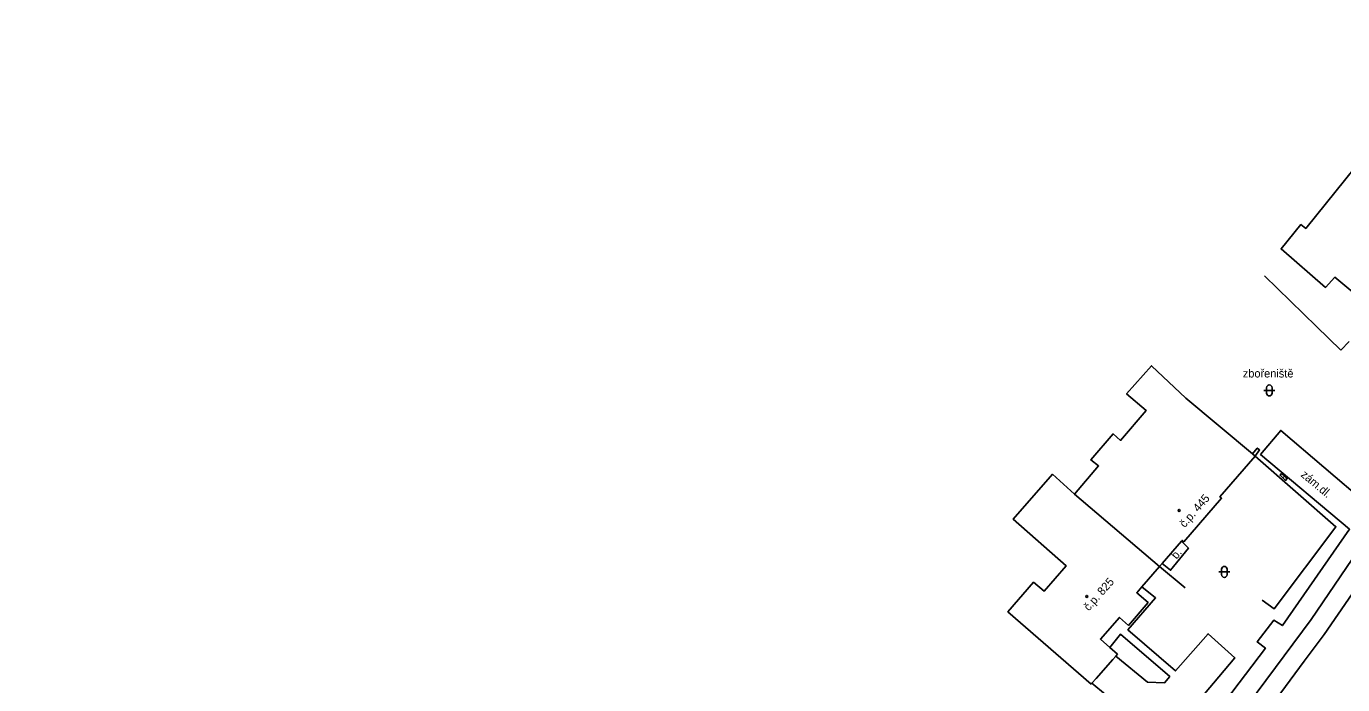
# Model space of a CAD drawing. Extents: x -577457 to -568404, y -1208466 to -1201387.
# Drawn here: x -569192.7 to -569072.5, y -1204568.7 to -1204508.6 of the extents above; entities that cross this region are included whole.
import ezdxf

# ---------------------------------------------------------------- set-up
doc = ezdxf.new("R2010")
doc.units = 0
for name, color, linetype in [('BUDOVY_MĚŘ', 7, 'Continuous'), ('BUDOVY_NEMĚŘ', 7, 'Continuous'), ('OBVOD_PILÍŘE', 7, 'Continuous'), ('POMOC_POPIS', 7, 'Continuous'), ('ROZHRANÍ_PLOCH', 7, 'Continuous'), ('ZN_BUDOV', 7, 'Continuous'), ('ZN_DOPLŇKOVÉ', 7, 'Continuous'), ('ZN_KULTUR', 7, 'Continuous'), ('Č_POPIS_ORIENT', 7, 'Continuous')]:
    doc.layers.add(name, color=color, linetype=linetype)

msp = doc.modelspace()

# ---------------------------------------------------------------- linework, layer by layer
at = {"layer": 'BUDOVY_MĚŘ'}
for points in [[(-569080.72, -1204547.68), (-569080.49, -1204547.88)], [(-569087.2, -1204555.63), (-569087.15, -1204555.57), (-569087.01, -1204555.69), (-569083.54, -1204551.72), (-569083.7, -1204551.59), (-569080.49, -1204547.88)], [(-569089.21, -1204557.96), (-569090.83, -1204559.82)], [(-569089.21, -1204557.96), (-569088.97, -1204557.68)], [(-569090.83, -1204559.82), (-569091.29, -1204560.36), (-569090.26, -1204561.25), (-569092.06, -1204563.33), (-569092.88, -1204562.61), (-569094.62, -1204564.58), (-569093.76, -1204565.34)], [(-569093.76, -1204565.34), (-569093.05, -1204565.97)], [(-569093.2, -1204566.15), (-569093.48, -1204566.46)], [(-569093.05, -1204565.97), (-569093.2, -1204566.15)], [(-569095.39, -1204568.62), (-569095.01, -1204568.19)], [(-569095.39, -1204568.62), (-569095.47, -1204568.71)]]:
    msp.add_lwpolyline(points, dxfattribs=at)
at = {"layer": 'BUDOVY_NEMĚŘ'}
for points in [[(-569071.32, -1204521.47), (-569075.86, -1204527.09), (-569076.3, -1204526.74), (-569078.11, -1204528.96), (-569074.05, -1204532.48), (-569073.21, -1204531.55), (-569069.56, -1204534.58)], [(-569080.72, -1204547.68), (-569086.8, -1204542.59), (-569089.96, -1204539.63), (-569092.23, -1204542.18), (-569090.45, -1204543.71), (-569092.78, -1204546.44), (-569093.46, -1204545.85), (-569095.48, -1204548.22), (-569094.78, -1204548.78), (-569096.99, -1204551.35)], [(-569096.99, -1204551.35), (-569098.98, -1204549.54), (-569102.6, -1204553.63), (-569097.73, -1204557.9), (-569099.76, -1204560.22), (-569100.72, -1204559.4), (-569103.07, -1204562.09), (-569095.47, -1204568.71)], [(-569096.99, -1204551.35), (-569089.21, -1204557.96)]]:
    msp.add_lwpolyline(points, dxfattribs=at)
at = {"layer": 'OBVOD_PILÍŘE'}
for points in [[(-569077.92, -1204549.59), (-569078.07, -1204549.46), (-569078.21, -1204549.62), (-569077.94, -1204549.87), (-569077.79, -1204549.71), (-569077.92, -1204549.59)], [(-569077.67, -1204549.82), (-569077.79, -1204549.71), (-569077.94, -1204549.87), (-569077.7, -1204550.09), (-569077.55, -1204549.93), (-569077.67, -1204549.82)]]:
    msp.add_lwpolyline(points, dxfattribs=at)
at = {"layer": 'ROZHRANÍ_PLOCH'}
for points in [[(-569041.21, -1204508.64), (-569040.59, -1204509.58), (-569040.25, -1204510.21), (-569039.93, -1204511.4), (-569039.84, -1204512.36), (-569040.05, -1204513.31), (-569040.29, -1204513.88), (-569040.51, -1204513.8), (-569043.68, -1204518.74), (-569050.87, -1204529.62), (-569059.42, -1204542.46), (-569063.61, -1204548.77), (-569066.83, -1204553.51), (-569074.19, -1204564.16), (-569076.01, -1204566.61), (-569079, -1204570.64)], [(-569193.54, -1204654.14), (-569180.57, -1204647.46), (-569168.09, -1204641.22), (-569155.65, -1204634.81), (-569151.19, -1204632.37), (-569146.32, -1204629.48), (-569140.18, -1204625.55), (-569133.63, -1204621.26), (-569127.76, -1204617.05), (-569123.45, -1204613.78), (-569117.55, -1204608.82), (-569108.26, -1204600.74), (-569100.71, -1204593.46), (-569095.2, -1204587.67), (-569088.24, -1204579.64), (-569082.76, -1204572.74), (-569075.37, -1204562.81), (-569068.38, -1204552.55), (-569060.81, -1204541.45), (-569052.52, -1204528.77), (-569045.02, -1204517.63), (-569041.38, -1204511.96), (-569040.25, -1204510.21)], [(-569065.63, -1204542.48), (-569065.75, -1204542.69), (-569064.6, -1204543.84), (-569070.27, -1204552.24), (-569078.14, -1204545.53), (-569079.98, -1204547.72), (-569071.85, -1204554.55), (-569077.99, -1204563.35), (-569078.76, -1204562.85), (-569080.29, -1204564.84), (-569079.54, -1204565.42), (-569085.02, -1204572.63)], [(-569088.97, -1204557.68), (-569088.21, -1204558.3), (-569086.57, -1204556.27), (-569087.2, -1204555.63)], [(-569090.83, -1204559.82), (-569089.58, -1204560.82), (-569092.11, -1204563.73), (-569087.76, -1204567.49), (-569084.78, -1204564.1), (-569082.33, -1204566.3), (-569086.56, -1204571.33), (-569087.6, -1204570.5), (-569087.76, -1204570.73), (-569085.69, -1204572.64), (-569085.43, -1204572.32), (-569085.02, -1204572.63)], [(-569093.76, -1204565.34), (-569092.79, -1204564.15), (-569088.28, -1204568.01), (-569088.75, -1204568.57), (-569090.32, -1204568.52), (-569093.2, -1204566.15)], [(-569095.39, -1204568.62), (-569090.4, -1204572.75), (-569089.94, -1204572.78), (-569087.13, -1204575.33)]]:
    msp.add_lwpolyline(points, dxfattribs=at)
at = {"layer": 'ZN_BUDOV'}
for centre in [(-569087.43, -1204552.84), (-569095.86, -1204560.69)]:
    msp.add_circle(centre, 0.0875, dxfattribs=at)
at = {"layer": 'ZN_DOPLŇKOVÉ'}
for points in [[(-569079.62, -1204531.41), (-569074.87, -1204536.05), (-569072.65, -1204538.22)], [(-569072.65, -1204538.22), (-569071.9, -1204537.41)], [(-569080.49, -1204547.88), (-569080.08, -1204547.32), (-569080.29, -1204547.15), (-569080.72, -1204547.68)], [(-569080.49, -1204547.88), (-569073.1, -1204554.33), (-569078.74, -1204561.81), (-569079.83, -1204561.03)], [(-569088.97, -1204557.68), (-569087.2, -1204555.63)], [(-569089.21, -1204557.96), (-569086.86, -1204559.9)], [(-569095.01, -1204568.19), (-569093.48, -1204566.46)]]:
    msp.add_lwpolyline(points, dxfattribs=at)
at = {"layer": 'ZN_KULTUR'}
for p, q in [((-569079.44, -1204542.13), (-569079.44, -1204541.63)), ((-569078.94, -1204542.13), (-569078.94, -1204541.63)), ((-569079.69, -1204541.88), (-569078.69, -1204541.88)), ((-569083.79, -1204558.45), (-569082.79, -1204558.45)), ((-569083.54, -1204558.7), (-569083.54, -1204558.2)), ((-569083.04, -1204558.7), (-569083.04, -1204558.2))]:
    msp.add_line(p, q, dxfattribs=at)
for centre, start, end in [((-569079.19, -1204541.63), 0, 180), ((-569079.19, -1204542.13), 180, 360), ((-569083.29, -1204558.2), 0, 180), ((-569083.29, -1204558.7), 180, 360)]:
    msp.add_arc(centre, 0.25, start, end, dxfattribs=at)

# ---------------------------------------------------------------- texts
at = {"layer": 'POMOC_POPIS'}
msp.add_text('zbořeniště', height=0.75, dxfattribs=at).set_placement((-569081.61, -1204540.7))
for s, rotation, p in [('zám.dl.', 319.9664, (-569076.37, -1204549.67)), ('b.', 51.0659, (-569087.65, -1204557.35))]:
    msp.add_text(s, height=0.75, rotation=rotation, dxfattribs=at).set_placement(p)
at = {"layer": 'Č_POPIS_ORIENT'}
for s, rotation, p in [('č.p. 445', 49.14, (-569086.91, -1204554.46)), ('č.p. 825', 48.54, (-569095.67, -1204562.07))]:
    msp.add_text(s, height=0.75, rotation=rotation, dxfattribs=at).set_placement(p)

doc.saveas('drawing.dxf')
